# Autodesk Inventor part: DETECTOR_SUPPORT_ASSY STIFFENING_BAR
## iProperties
Shininess: 64.0
Length Units: 11272
Angle Units: 11279
Time Units: 11290
Mass Units: 11286
Length Display Precision: 3
Angle Display Precision: 2
Compacted: True
Part Number: DETECTOR_SUPPORT_ASSY STIFFENING_BAR
Document SubType Name: Modeling
Created: 2004-08
Designer: John Blackburn
Material: MILD_STEEL
Manufacturer: Standard
Standards Organization: Custom
Density: 0.0
Volumn: 0.0
Area: 0.0
PropertySet Name: Model Information
Control State: 0
Master: False
Checked Out: False
Author: John Blackburn
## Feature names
1. ExtrusionMidplane1
